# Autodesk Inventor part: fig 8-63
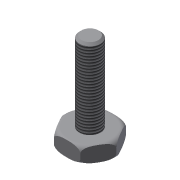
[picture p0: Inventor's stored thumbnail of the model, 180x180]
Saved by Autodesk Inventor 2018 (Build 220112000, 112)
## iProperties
Shininess: 77.0
Length Units: 11269
Angle Units: 11279
Time Units: 11290
Mass Units: 11283
Length Display Precision: 3
Angle Display Precision: 2
Created: 2002-01
Part Number: fig 8-63
Document SubType Name: Modeling
Designer: ***
Density: 1 g/cm^3
Material: Generic
Appearance: Default
Density: 0.0
Volumn: 0.0
Area: 0.0
PropertySet Name: Model Information
Control State: 0
Master: False
Checked Out: False
Author: ***
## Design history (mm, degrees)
sketch "Sketch1"
  geometry: C1 r 25 at (0, 0)
  constraints: 1 centre point
  dimensions: "d0" = 50 diameter of C1
extrude "Extrusion1" new body sketch "Sketch1" distance "d1" = 15; taper "d2" = 0 deg
fillet "Fillet1" dims "d3" = 5
sketch "Sketch2"
  geometry: L1 (25.058, 0)-(12.529, -21.701); L2 (12.529, -21.701)-(-12.529, -21.701); L3 (-12.529, -21.701)-(-25.058, 0); L4 (-25.058, 0)-(-12.529, 21.701); L5 (-12.529, 21.701)-(12.529, 21.701); L6 (12.529, 21.701)-(25.058, 0); 1 further point
  constraints: 12 end point, 11 other
extrude "Extrusion2" sketch "Sketch2" extent not by distance; stored distance "d4" = 15; taper "d5" = 0 deg
sketch "Sketch3"
  geometry: C1 r 10.044 at (0, 0); 1 further point
  constraints: 1 centre point, 1 coincident
extrude "Extrusion3" join sketch "Sketch3" distance "d6" = 75; taper "d7" = 0 deg
chamfer "Chamfer1" distance "d8" = 2; stored, may be unused: second distance "d9" = 2, angle "d16" = 45 deg
thread "Thread3" dims "d14" = 30, "d15" = 0
body "Solid1"
